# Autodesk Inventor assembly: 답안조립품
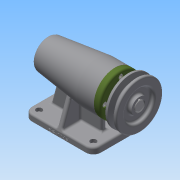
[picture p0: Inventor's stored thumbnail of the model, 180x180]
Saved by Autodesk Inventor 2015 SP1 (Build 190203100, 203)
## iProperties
Created: 2018-09
Part Number: 답안조립품
Document SubType Name: Assembly
Designer: Administrator
Author: Administrator
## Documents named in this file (12)
- D:\Users\Administrator\Desktop\480907V1027\답안조립품.iam
- D:\Users\Administrator\Desktop\480907V1027\1-본체.ipt
- D:\Users\Administrator\Desktop\480907V1027\커버.ipt
- D:\Users\Administrator\Desktop\480907V1027\베어링 6004.ipt
- D:\Users\Administrator\Desktop\480907V1027\오일 실.ipt
- D:\Users\Administrator\Desktop\480907V1027\축.ipt
- D:\Users\Administrator\Desktop\480907V1027\키 5 x 5 x 16.ipt
- D:\Users\Administrator\Desktop\480907V1027\멈춤나사 M3.ipt
- D:\Users\Administrator\Desktop\480907V1027\V벨트풀리.ipt
- D:\Users\Administrator\Desktop\480907V1027\어댑터슬리브.ipt
- D:\Users\Administrator\Desktop\480907V1027\베어링 51202.ipt
- D:\Users\Administrator\Desktop\480907V1027\볼트 M4.ipt
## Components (2 placed, 2 different names)
1. 1-본체:1
2. V벨트풀리:1 — 플러쉬:1
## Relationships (1: Flush 1)
- 플러쉬:1 [Flush]: V벨트풀리:1
